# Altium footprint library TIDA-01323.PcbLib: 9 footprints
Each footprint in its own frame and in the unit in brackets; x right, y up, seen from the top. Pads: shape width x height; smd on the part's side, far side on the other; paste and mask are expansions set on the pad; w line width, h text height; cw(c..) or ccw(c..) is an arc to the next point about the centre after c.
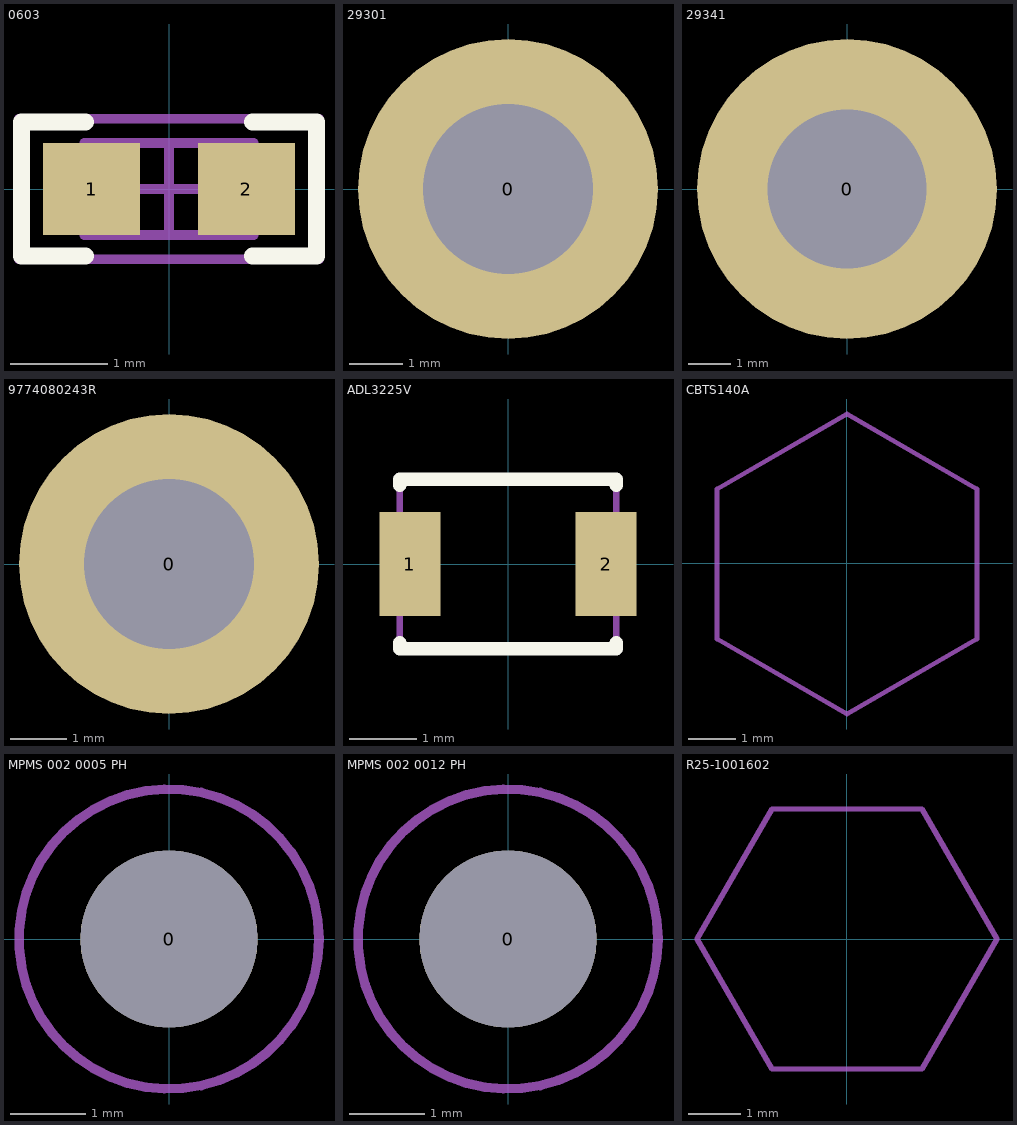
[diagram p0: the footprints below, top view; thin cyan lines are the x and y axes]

## 0603 [mm] "0603"
height 0.55
pads (2):
  rect 1x0.95 smd: 1(-0.8,0) 2(0.8,0)
Top Overlay:
  lines w0.178: -0.864,-0.691 -1.524,-0.691 -1.524,0.693 -0.864,0.693 ; 0.864,-0.691 1.524,-0.691 1.524,0.693 0.864,0.693
M5 Assembly Top:
  lines w0.1: -1.55,-0.725 -1.55,0.725 1.55,0.725 1.55,-0.725 -1.55,-0.725
  text ".Designator" at -1.397,-0.381 h0.76
M13 Component Bodies Top:
  lines w0.1: -0.55,-0.475 -0.55,0.475 ; 0.55,-0.475 0.55,0.475 ; -0.875,-0.475 0.875,-0.475 0.875,0.475 -0.875,0.475 -0.875,-0.475
M15 Courtyards Top:
  lines w0.1: -0.475,0 0.475,0 ; 0,-0.475 0,0.475 ; -1.55,-0.725 1.55,-0.725 1.55,0.725 -1.55,0.725 -1.55,-0.725
3D body: height 0.55, standoff 0, extent -0.874,-0.474 -0.551,0.474
3D body: height 0.55, standoff 0, extent -0.549,-0.474 0.549,0.474
3D body: height 0.55, standoff 0, extent 0.551,-0.474 0.874,0.474

## 29301 [mm] "MACHINE SCREW PAN SLOTTED M2.5"
height 1.4
pads (1):
  round 5.6 hole 3.175: 0(0,0)
M5 Assembly Top:
  circle w0.1: c0,0 r2.525
  text ".Designator" at -1.708,-0.368 h1.02
3D body "keystone-PN29301.STEP": height 1.41, standoff -5.99, extent -2.4,-2.4 2.4,2.4

## 29341 [mm] "MACHINE SCREW PAN SLOTTED M3"
height 1.7
pads (1):
  round 7 hole 3.7: 0(0,0)
M5 Assembly Top:
  circle w0.1: c0,0 r2.825
  text ".Designator" at -1.661,-0.39 h1.02
3D body "keystone-PN29341.STEP": height 1.71, standoff -5.99, extent -2.64,-2.64 2.76,2.76

## 9774080243R [mm] "ROUND STANDOFF M2 STEEL 8MM"
height 8.1
pads (1):
  round 5.3 hole 3 unplated: 0(0,0)
M5 Assembly Top:
  circle w0.1: c0,0 r2.175
  text ".Designator" at -1.5,-0.5 h1.02
3D body "STEP-9774080243R-rev1 (1).stp": height 8.01, standoff -1.39, extent -2.175,-2.174 2.175,2.174

## ADL3225V [mm] "SMD, 2-Leads, Body 3.2x2.5mm"
height 2.4
pads (2):
  rect 0.9x1.53 smd: 1(-1.45,0) 2(1.45,0)
Top Overlay:
  lines w0.2: -1.6,-1.165 -1.6,-1.25 1.6,-1.25 1.6,-1.165 ; -1.6,1.165 -1.6,1.25 1.6,1.25 1.6,1.165
M5 Assembly Top:
  lines w0.1: -1.6,-1.25 -1.6,1.25 1.6,1.25 1.6,-1.25 -1.6,-1.25
  text ".Designator" at -1.4,-0.5 h0.76
3D body: height 2.4, standoff 1.8, extent -1.6,-1.25 1.6,1.25
3D body: height 1.8, standoff 0.02, extent -1.599,-1.249 -1.001,1.249
3D body: height 1.8, standoff 0, extent -0.999,-0.899 0.999,0.899
3D body: height 1.8, standoff 0.02, extent 1.001,-1.249 1.599,1.249
3D body: height 0.65, standoff 0, extent -1.599,-0.679 -1.001,0.679
3D body: height 0.65, standoff 0, extent -1.599,-0.679 -1.551,0.679
3D body: height 0.65, standoff 0, extent -1.61,-0.68 -1,0.68
3D body: height 0.65, standoff 0, extent 1,-0.68 1.61,0.68

## CBTS140A [mm] "HEX STANDOFF M3 NYLON 40MM"
height 40
M5 Assembly Top:
  lines w0.1: -2.75,-1.6 0,-3.188 2.75,-1.6 2.75,1.575 0,3.163 -2.75,1.575 -2.75,-1.6
  text ".Designator" at -1.775,-0.3 h1.02
3D body "CBTS140A.stp": height 0, standoff -40, extent -2.756,-3.182 2.756,3.182

## MPMS 002 0005 PH [mil] "MACHINE SCREW PAN PHILLIPS M2"
height 67.72
pads (1):
  round 93 hole 93 unplated: 0(0,0)
M5 Assembly Top:
  circle w5: c0,0 r78.74
  text ".Designator" at -66.93,-15.75 h40
3D body: height 0, standoff -196.85, extent -41.33,-41.31 41.34,41.32
3D body: height 67.72, standoff 0, extent -78.73,-78.71 78.75,78.73

## MPMS 002 0012 PH [mil] "MACHINE SCREW PAN PHILLIPS M2"
height 67.72
pads (1):
  round 93 hole 93 unplated: 0(0,0)
M5 Assembly Top:
  circle w5: c0,0 r78.74
  text ".Designator" at -66.93,-15.75 h40
3D body: height 0, standoff -472.44, extent -41.33,-41.27 41.34,41.28
3D body: height 67.72, standoff 0, extent -78.73,-78.71 78.75,78.73

## R25-1001602 [mm] "HEX STANDOFF M2.5 BRASS 16MM"
height 16
M5 Assembly Top:
  lines w0.1: -2.887,0 -1.443,-2.5 1.443,-2.5 2.887,0 1.443,2.5 -1.443,2.5 -2.887,0
  text ".Designator" at -1.673,-0.371 h1.02
3D body: height 16, standoff 0, extent -2.887,-2.501 2.887,2.501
